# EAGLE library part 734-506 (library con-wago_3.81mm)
Serie 734, Federleiste mit geraden Einlötstiften / Series 734, Female connector with straight solder pins Polzahl / Pole No.: 6 Bemessungsspannung / Rated Voltage: 160 V Nennstrom / Nominal Current: 10 A Lötstiftlänge: / Solder Pin Length: 3.8 mm Farbe / Color: orange / orange Stand: 01.01.2012. Die jeweils aktuellen Daten zu diesem Artikel finden Sie in unserem Produktkatalog, den Sie unter www.wago.com einsehen können. As of: 01/01/2012. Please find the newest data for this article in our product catalogue, which can be viewed under www.wago.com.
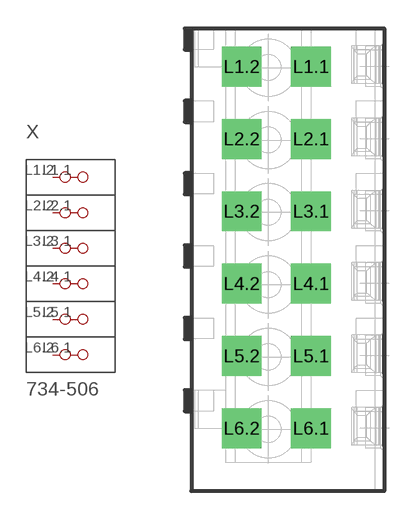
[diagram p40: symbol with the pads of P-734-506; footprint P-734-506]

Designator prefix X

## 734-506  [P-734-506]
L1.1  P1.1
L1.2  P1.2
L2.1  P2.1
L2.2  P2.2
L3.1  P3.1
L3.2  P3.2
L4.1  P4.1
L4.2  P4.2
L5.1  P5.1
L5.2  P5.2
L6.1  P6.1
L6.2  P6.2

## Footprint P-734-506 (pad centres in mm)
drill 1.4 square: L1.1 1.26,10.17; L1.2 -2.39,10.17; L2.1 1.26,6.36; L2.2 -2.39,6.36; L3.1 1.26,2.55; L3.2 -2.39,2.55; L4.1 1.26,-1.26; L4.2 -2.39,-1.26; L5.1 1.26,-5.07; L5.2 -2.39,-5.07; L6.1 1.26,-8.88; L6.2 -2.39,-8.88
